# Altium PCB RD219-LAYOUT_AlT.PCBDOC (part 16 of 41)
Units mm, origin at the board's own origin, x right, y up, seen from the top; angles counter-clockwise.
Board outline 209.75 x 159.97 mm, 2 copper layers (TOP, BOTTOM), stack 0 mm thick; 398 components, 199 nets, 1469 pads, 0 vias.
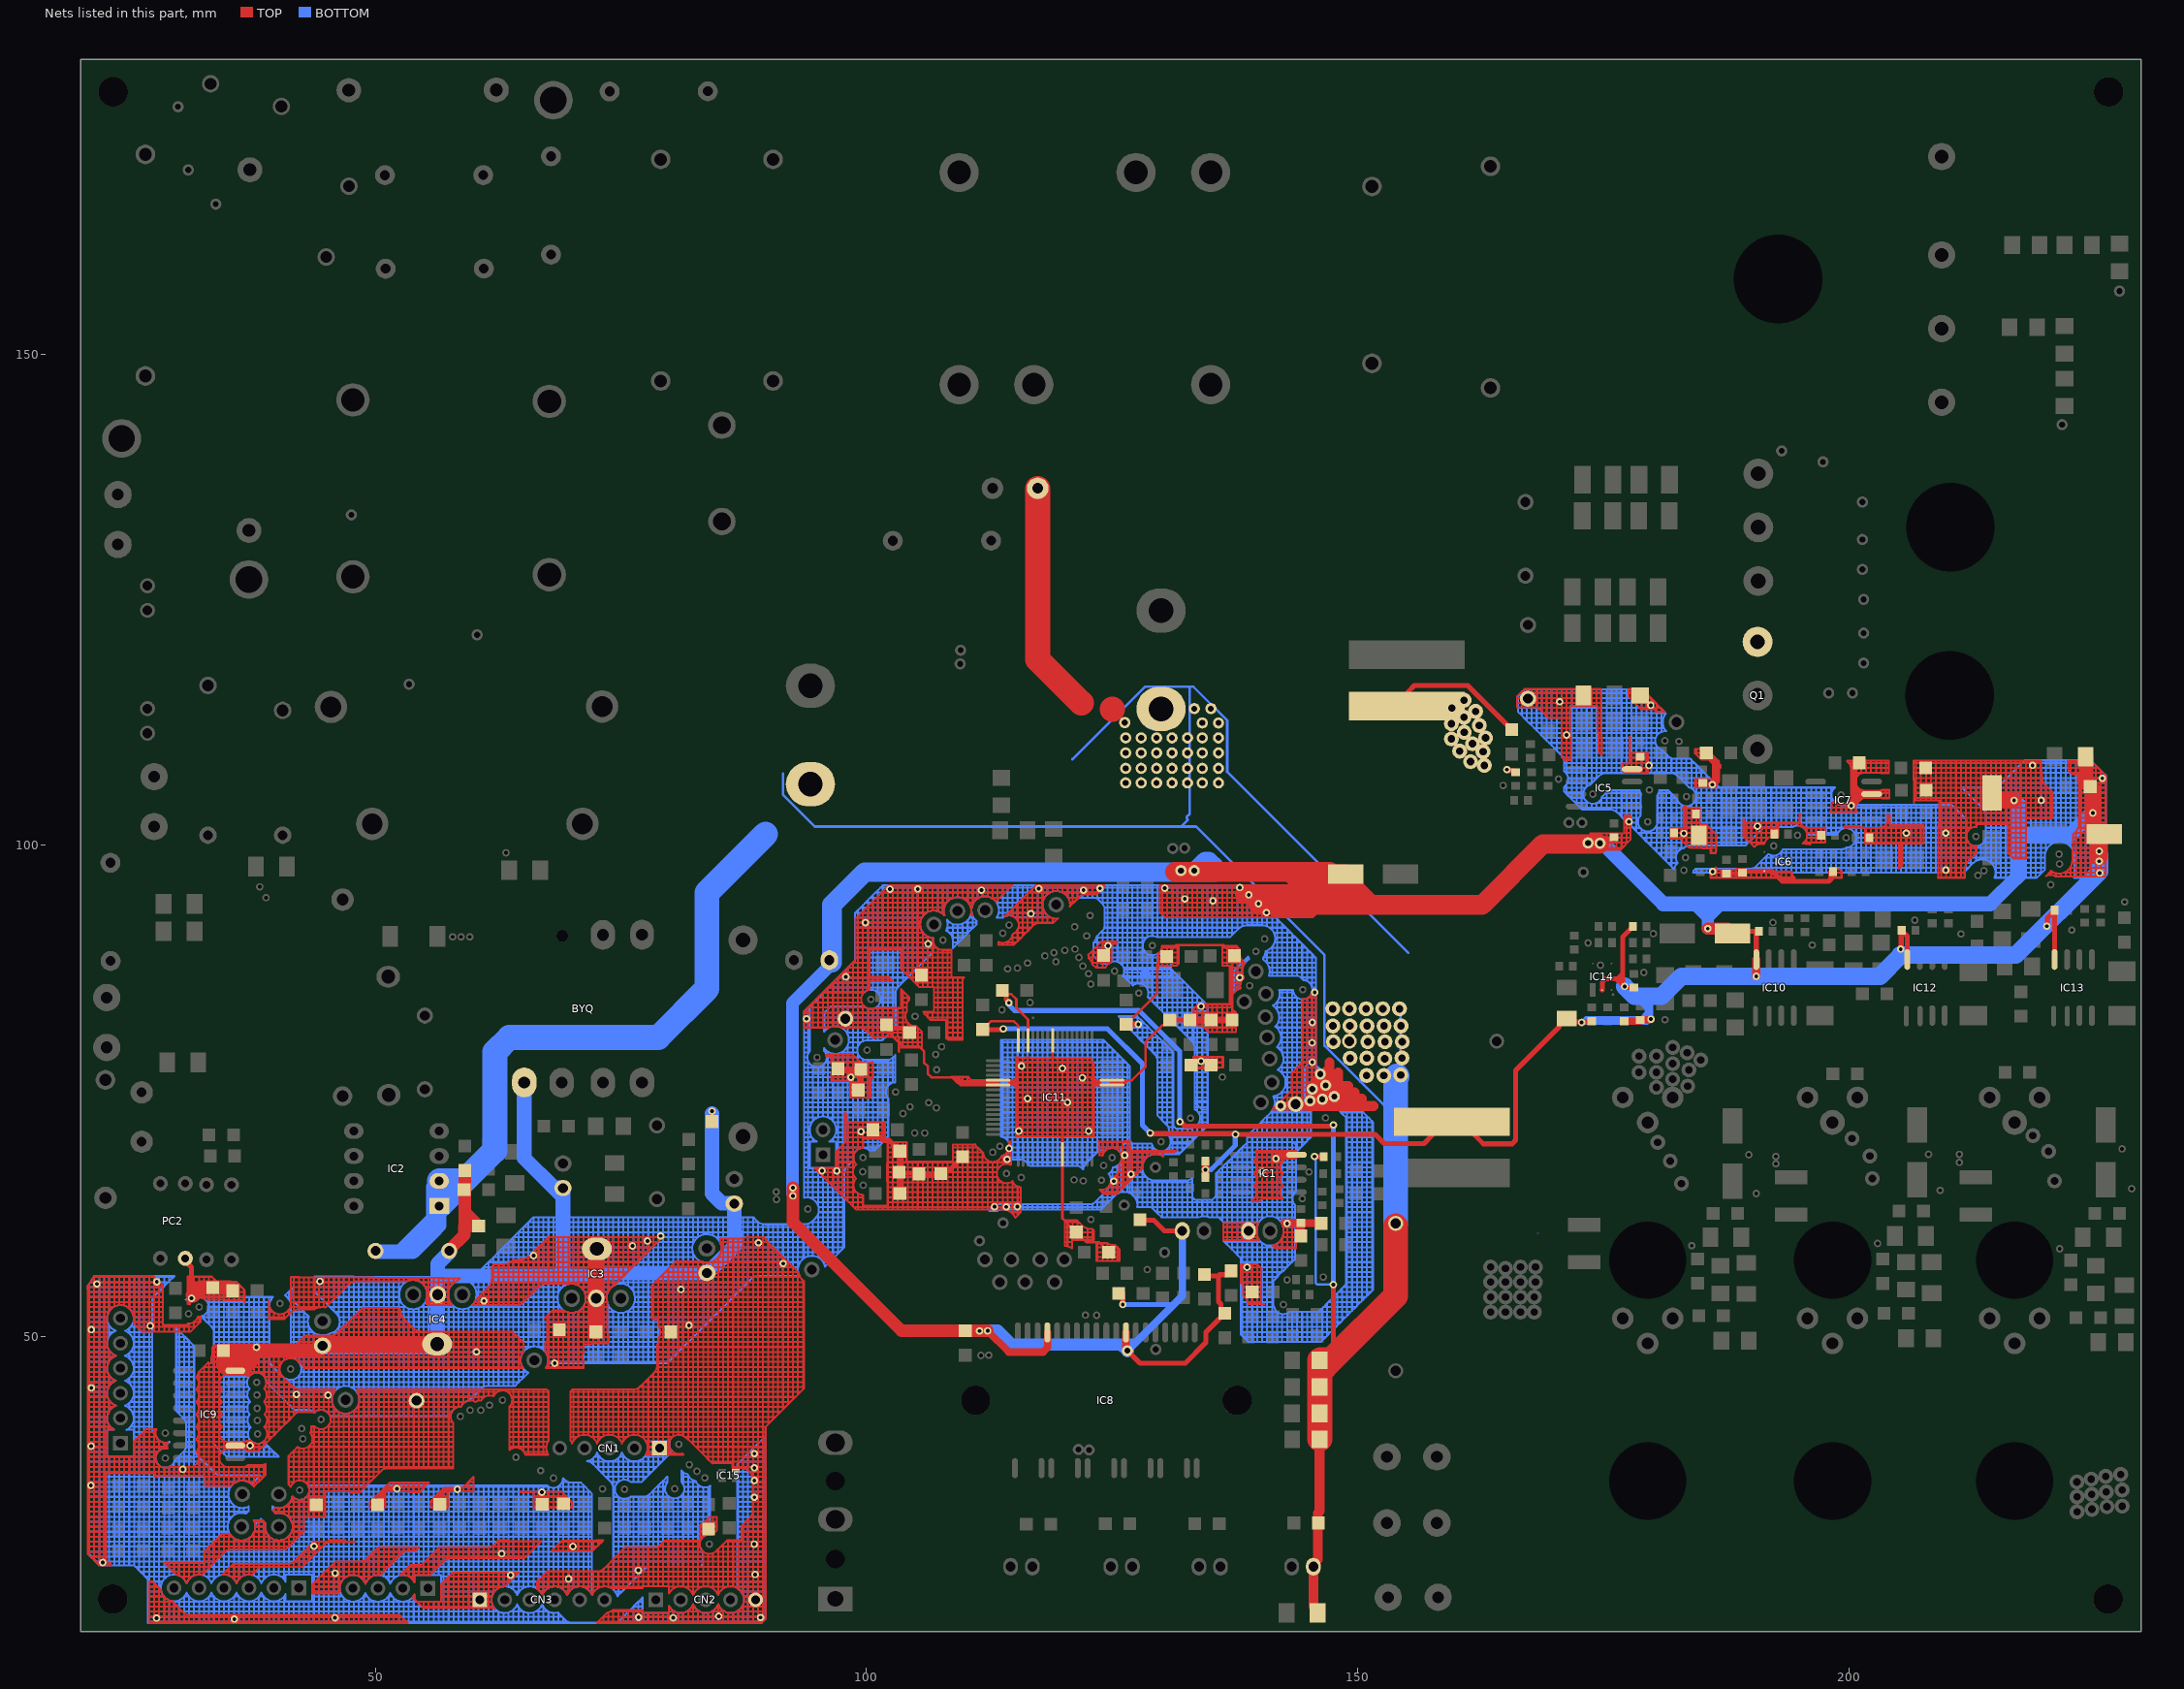
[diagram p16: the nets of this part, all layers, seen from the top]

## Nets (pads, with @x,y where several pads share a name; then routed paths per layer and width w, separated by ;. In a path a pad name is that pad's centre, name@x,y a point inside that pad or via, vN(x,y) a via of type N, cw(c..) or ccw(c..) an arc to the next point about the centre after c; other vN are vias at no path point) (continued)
GND: (continued)
  TOP w0.203: 145.349,75.88 145.349,76.388 ; 145.349,75.88 145.688,75.88 145.73,75.88 ; 145.349,76.388 145.349,76.896 ; 145.349,76.388 pad.@145.73,76.388 ; 145.349,76.896 145.349,77.404 ; 145.349,76.896 pad.@145.73,76.896 ; 145.349,77.404 pad.@145.349,77.912 ; 145.349,77.404 145.73,77.404 ; pad.@145.349,77.912 pad.@145.73,77.912 ; pad.@145.349,77.912 145.349,78.42 ; 145.349,78.42 145.349,78.928 ; 145.349,78.42 145.73,78.42 ; 145.349,78.928 145.349,79.436 ; 145.349,78.928 145.73,78.928 ; 145.349,79.436 145.73,79.436 ; 145.349,79.436 pad.@145.349,79.944 ; pad.@145.349,79.944 145.349,80.452 ; pad.@145.349,79.944 145.73,79.944 ; 145.349,80.452 145.349,80.96 ; 145.349,80.452 145.73,80.452 ; 145.349,80.96 145.349,81.468 ; 145.349,80.96 145.73,80.96 ; 145.349,81.468 pad.@145.349,81.976 ; 145.349,81.468 145.73,81.468 ; pad.@145.349,81.976 pad.@145.73,81.976 ; pad.@145.349,81.976 145.349,82.484 ; 145.349,82.484 145.349,82.992 ; 145.349,82.484 145.73,82.484 ; 145.349,82.992 145.349,83.5 ; 145.349,82.992 145.73,82.992 ; 145.349,83.5 145.349,84.008 ; 145.349,83.5 145.73,83.5 ; 145.349,84.008 145.349,84.516 ; 145.349,84.008 145.73,84.008 ; 145.349,84.516 pad.@145.349,85.006 ; 145.349,84.516 145.73,84.516 ; pad.@145.349,85.006 145.73,85.006 145.73,84.516 ; 145.73,74.356 145.73,74.833 pad.@145.73,74.864 ; pad.@145.73,74.864 pad.@145.73,75.372 ; pad.@145.73,75.372 145.73,75.392 145.73,75.88 ; 145.73,75.88 145.73,75.922 pad.@145.73,76.388 ; pad.@145.73,76.388 pad.@145.73,76.896 ; pad.@145.73,76.896 145.73,77.404 ; 145.73,77.404 pad.@145.73,77.912 ; pad.@145.73,77.912 145.73,78.42 ; 145.73,78.42 145.73,78.928 ; 145.73,78.928 145.73,79.436 ; 145.73,79.436 145.73,79.944 ; 145.73,79.944 145.73,80.452 ; 145.73,80.452 145.73,80.96 ; 145.73,80.96 145.73,81.468 ; 145.73,81.468 pad.@145.73,81.976 ; pad.@145.73,81.976 145.73,82.484 ; 145.73,82.484 145.73,82.992 ; 145.73,82.992 145.73,83.5 ; 145.73,83.5 145.73,84.008 ; 145.73,84.008 145.73,84.516 ; 166.211,114.488 166.211,114.996 ; 166.211,114.488 C62.1@166.685,114.488 ; 166.211,114.488 166.211,114.07 166.685,114.07 ; 166.211,114.996 166.211,115.153 166.562,115.504 ; 166.211,114.996 C62.1@166.685,114.996 ; 166.562,115.504 166.685,115.627 ; 166.562,115.504 166.685,115.504 ; 166.685,114.07 167.193,114.07 ; 166.685,114.07 C62.1@166.685,114.488 ; C62.1@166.685,114.488 C62.1@167.193,114.488 ; C62.1@166.685,114.488 C62.1@166.685,114.996 ; C62.1@166.685,114.996 166.685,115.504 ; C62.1@166.685,114.996 C62.1@167.193,114.996 ; 166.685,115.504 166.685,115.627 ; 166.685,115.504 C62.1@167.193,115.504 ; 166.685,115.627 166.973,115.915 167.193,115.915 ; 167.193,114.07 C62.1@167.193,114.488 ; 167.193,114.07 167.701,114.07 ; C62.1@167.193,114.488 C62.1@167.193,114.996 ; C62.1@167.193,114.488 C62.1@167.701,114.488 ; C62.1@167.193,114.996 C62.1@167.193,115.504 ; C62.1@167.193,114.996 C62.1@167.701,114.996 ; C62.1@167.193,115.504 167.193,115.915 ; C62.1@167.193,115.504 C62.1@167.701,115.504 ; 167.193,115.915 167.701,115.915 ; 167.701,114.07 C62.1@167.701,114.488 ; 167.701,114.07 167.955,114.07 ; C62.1@167.701,114.488 168.209,114.488 ; C62.1@167.701,114.488 C62.1@167.701,114.996 ; C62.1@167.701,114.996 C62.1@167.701,115.504 ; C62.1@167.701,114.996 168.209,114.996 ; C62.1@167.701,115.504 167.701,115.915 ; C62.1@167.701,115.504 168.209,115.504 ; 167.701,115.915 168.209,115.915 ; 167.955,114.07 cw(c167.955,113.218) 168.209,114.031 ; 167.955,114.07 cw(c167.955,113.218) 168.209,114.031 ; 168.209,114.031 cw(c167.955,113.218) 168.335,113.98 ; 168.209,114.031 cw(c167.955,113.218) 168.335,113.98 ; 168.209,114.031 168.209,114.488 ; 168.209,114.488 168.717,114.488 ; 168.209,114.488 168.209,114.996 ; 168.209,114.996 168.209,115.504 ; 168.209,114.996 168.717,114.996 ; 168.209,115.504 168.209,115.915 ; 168.209,115.504 168.717,115.504 ; 168.209,115.915 168.717,115.915 ; 168.335,113.98 cw(c167.955,113.218) 168.342,113.977 ; 168.335,113.98 cw(c167.955,113.218) 168.557,113.82 ccw(c167.955,113.218) 168.342,113.977 ; 168.335,113.98 cw(c167.955,113.218) 168.342,113.977 ; 168.335,113.98 168.717,113.98 ; 168.717,113.66 168.905,113.472 ; 168.717,113.66 168.717,113.98 ; 168.717,113.98 168.717,114.488 ; 168.717,113.98 169.225,113.98 ; 168.717,114.488 168.717,114.996 ; 168.717,114.488 169.225,114.488 ; 168.717,114.996 168.717,115.504 ; 168.717,114.996 169.225,114.996 ; 168.717,115.504 168.717,115.915 ; 168.717,115.504 169.225,115.504 ; 168.717,115.915 169.225,115.915 ; 168.905,113.472 169.225,113.472 ; 168.905,113.472 169.225,113.152 ; 169.225,113.152 169.413,112.964 ; 169.225,113.152 169.225,113.472 ; 169.225,113.472 169.225,113.98 ; 169.225,113.472 169.733,113.472 ; 169.225,113.98 169.225,114.488 ; 169.225,113.98 169.733,113.98 ; 169.225,114.488 169.225,114.996 ; 169.225,114.488 169.733,114.488 ; 169.225,114.996 169.225,115.504 ; 169.225,114.996 169.733,114.996 ; 169.225,115.504 169.225,115.915 ; 169.225,115.504 169.733,115.504 ; 169.225,115.915 169.733,115.915 ; 169.413,112.964 169.432,112.946 169.733,112.946 ; 169.413,112.964 169.733,112.964 ; 169.733,112.946 169.733,112.964 ; 169.733,112.946 170.241,112.946 ; 169.733,112.964 169.733,113.472 ; 169.733,112.964 170.241,112.964 ; 169.733,113.472 169.733,113.98 ; 169.733,113.472 170.241,113.472 ; 169.733,113.98 169.733,114.488 ; 169.733,113.98 170.241,113.98 ; 169.733,114.488 169.733,114.996 ; 169.733,114.488 pad.@170.241,114.488 ; 169.733,114.996 169.733,115.504 ; 169.733,114.996 170.241,114.996 ; 169.733,115.504 169.733,115.915 ; 169.733,115.504 170.241,115.504 ; 169.733,115.915 170.241,115.915 ; 170.241,112.946 170.241,112.964 ; 170.241,112.946 170.731,112.946 170.731,112.456 ; 170.241,112.964 170.749,112.964 ; 170.241,112.964 170.241,113.472 ; 170.241,113.472 170.241,113.98 ; 170.241,113.472 170.749,113.472 ; 170.241,113.98 pad.@170.241,114.488 ; 170.241,113.98 170.749,113.98 ; pad.@170.241,114.488 170.241,114.996 ; pad.@170.241,114.488 pad.@170.749,114.488 ; 170.241,114.996 170.241,115.504 ; 170.241,114.996 170.749,114.996 ; 170.241,115.504 170.241,115.915 ; 170.241,115.504 170.749,115.504 ; 170.241,115.915 170.749,115.915 ; 170.731,109.408 170.749,109.408 ; 170.731,109.408 170.731,109.916 ; 170.731,109.408 170.731,108.983 170.749,108.964 ; 170.731,109.916 170.731,110.424 ; 170.731,109.916 170.749,109.916 ; 170.731,110.424 170.749,110.424 ; 170.731,110.932 170.749,110.932 ; 170.731,110.932 170.731,111.44 ; 170.731,111.44 170.749,111.44 ; 170.731,111.44 170.731,111.948 ; 170.731,111.948 170.749,111.948 ; 170.731,111.948 170.731,112.456 ; 170.731,112.456 170.749,112.456 ; 170.749,108.964 170.813,108.9 ; 170.749,108.964 170.749,109.408 ; 170.749,109.408 170.749,109.916 ; 170.749,109.408 171.257,109.408 ; 170.749,109.916 170.749,110.424 ; 170.749,109.916 171.257,109.916 ; 170.749,110.424 171.257,110.424 ; 170.749,110.424 170.749,110.932 ; 170.749,110.932 170.749,111.44 ; 170.749,110.932 pad.@171.257,110.932 ; 170.749,111.44 170.749,111.948 ; 170.749,111.44 pad.@171.257,111.44 ; 170.749,111.948 170.749,112.456 ; 170.749,111.948 171.257,111.948 ; 170.749,112.456 170.749,112.964 ; 170.749,112.456 171.257,112.456 ; 170.749,112.964 171.257,112.964 ; 170.749,112.964 170.749,113.472 ; 170.749,113.472 170.749,113.98 ; 170.749,113.472 171.257,113.472 ; 170.749,113.98 pad.@170.749,114.488 ; 170.749,113.98 171.257,113.98 ; pad.@170.749,114.488 171.257,114.488 ; pad.@170.749,114.488 170.749,114.996 ; 170.749,114.996 171.257,114.996 ; 170.749,114.996 170.749,115.504 ; 170.749,115.504 170.749,115.915 ; 170.749,115.504 171.257,115.504 ; 170.749,115.915 171.257,115.915 ; 170.813,108.9 171.257,108.9 ; 171.257,108.634 cw(c171.467,107.757) 171.467,108.659 171.706,108.659 171.706,108.9 ; 171.257,108.634 171.257,108.9 ; 171.257,108.9 171.706,108.9 ; 171.257,108.9 171.257,109.408 ; 171.257,109.408 171.257,109.916 ; 171.257,109.408 171.706,109.408 ; 171.257,109.916 171.257,110.424 ; 171.257,109.916 171.706,109.916 ; 171.257,110.424 pad.@171.257,110.932 ; 171.257,110.424 171.706,110.424 ; pad.@171.257,110.932 171.706,110.932 ; pad.@171.257,110.932 pad.@171.257,111.44 ; pad.@171.257,111.44 171.257,111.948 ; pad.@171.257,111.44 171.579,111.44 ; 171.257,111.948 171.257,112.456 ; 171.257,111.948 171.579,111.948 ; 171.257,112.456 171.257,112.964 ; 171.257,112.456 171.579,112.456 ; 171.257,112.964 171.257,113.472 ; 171.257,112.964 171.579,112.964 ; 171.257,113.472 171.257,113.98 ; 171.257,113.472 171.579,113.472 ; 171.257,113.98 171.257,114.488 ; 171.257,113.98 171.579,113.98 ; 171.257,114.488 171.257,114.996 ; 171.257,114.488 171.765,114.488 ; 171.257,114.996 171.765,114.996 ; 171.257,114.996 171.257,115.504 ; 171.257,115.504 171.257,115.915 ; 171.257,115.504 171.765,115.504 ; 171.257,115.915 171.765,115.915 ; 171.579,111.44 171.579,111.948 ; 171.579,111.44 171.579,110.981 171.706,110.981 171.706,110.932 ; 171.579,111.948 171.579,112.456 ; 171.579,112.456 171.579,112.964 ; 171.579,112.964 171.579,113.472 ; 171.579,113.472 171.579,113.98 ; 171.579,113.98 171.579,114.185 171.765,114.185 ; 171.706,108.9 171.706,109.408 ; 171.706,109.408 171.706,109.916 ; 171.706,109.916 171.706,110.424 ; 171.706,110.424 171.706,110.932 ; 171.765,114.185 172.273,114.185 ; 171.765,114.185 171.765,114.488 ; 171.765,114.488 171.765,114.996 ; 171.765,114.488 ZD8.1@172.273,114.488 ; 171.765,114.996 ZD8.1@172.273,114.996 ; 171.765,114.996 171.765,115.504 ; 171.765,115.504 171.765,115.915 ; 171.765,115.504 ZD8.1@172.273,115.504 ; 171.765,115.915 ZD8.1@172.273,115.915 ; 172.273,114.185 ZD8.1@172.273,114.488 ; 172.273,114.185 172.781,114.185 ; ZD8.1@172.273,114.488 ZD8.1@172.273,114.996 ; ZD8.1@172.273,114.488 ZD8.1@172.781,114.488 ; ZD8.1@172.273,114.996 ZD8.1@172.781,114.996 ; ZD8.1@172.273,114.996 ZD8.1@172.273,115.504 ; ZD8.1@172.273,115.504 ZD8.1@172.273,115.915 ; ZD8.1@172.273,115.504 ZD8.1@172.781,115.504 ; ZD8.1@172.273,115.915 ZD8.1@172.781,115.915 ; 172.781,114.185 ZD8.1@172.781,114.488 ; 172.781,114.185 173.289,114.185 ; ZD8.1@172.781,114.488 ZD8.1@172.781,114.996 ; ZD8.1@172.781,114.488 ZD8.1@173.289,114.488 ; ZD8.1@172.781,114.996 ZD8.1@172.781,115.504 ; ZD8.1@172.781,114.996 ZD8.1@173.289,114.996 ; ZD8.1@172.781,115.504 ZD8.1@172.781,115.915 ; ZD8.1@172.781,115.504 ZD8.1@173.289,115.504 ; ZD8.1@172.781,115.915 ZD8.1@173.289,115.915 ; 173.289,114.185 ZD8.1@173.289,114.488 ; 173.289,114.185 173.797,114.185 ; ZD8.1@173.289,114.488 ZD8.1@173.289,114.996 ; ZD8.1@173.289,114.488 173.797,114.488 ; ZD8.1@173.289,114.996 173.797,114.996 ; ZD8.1@173.289,114.996 ZD8.1@173.289,115.504 ; ZD8.1@173.289,115.504 ZD8.1@173.289,115.915 ; ZD8.1@173.289,115.504 173.797,115.504 ; ZD8.1@173.289,115.915 173.797,115.915 ; 173.797,101.026 174.051,100.772 ; 173.797,101.026 173.797,101.213 ; 173.797,101.213 174.305,101.213 ; 173.797,114.185 174.305,114.185 ; 173.797,114.185 173.797,114.488 ; 173.797,114.488 173.797,114.996 ; 173.797,114.488 174.305,114.488 ; 173.797,114.996 174.305,114.996 ; 173.797,114.996 173.797,115.504 ; 173.797,115.504 173.797,115.915 ; 173.797,115.504 174.305,115.504 ; 173.797,115.915 174.305,115.915 ; 174.051,100.772 174.305,100.772 ; 174.051,100.772 pad.@174.305,100.518 ; pad.@174.305,100.518 174.305,100.772 ; pad.@174.305,100.518 pad.@174.559,100.264 ; 174.305,100.772 174.305,101.213 ; 174.305,100.772 174.813,100.772 ; 174.305,101.213 174.813,101.213 ; 174.305,114.185 174.383,114.185 174.383,113.98 ; 174.305,114.185 174.305,114.488 ; 174.305,114.488 174.305,114.996 ; 174.305,114.488 174.735,114.488 ; 174.305,114.996 174.735,114.996 ; 174.305,114.996 174.305,115.504 ; 174.305,115.504 174.305,115.915 ; 174.305,115.504 174.735,115.504 ; 174.305,115.915 174.735,115.915 174.735,115.504 ; 174.383,111.948 174.383,112.456 ; 174.383,111.948 174.383,111.518 174.51,111.518 174.51,111.44 ; 174.383,111.948 174.735,111.948 ; 174.383,112.456 174.383,112.964 ; 174.383,112.456 174.735,112.456 ; 174.383,112.964 174.383,113.472 ; 174.383,112.964 174.735,112.964 ; 174.383,113.472 174.383,113.98 ; 174.383,113.472 174.735,113.472 ; 174.383,113.98 174.735,113.98 ; 174.51,109.916 174.813,109.916 ; 174.51,109.916 174.51,110.424 ; 174.51,109.916 174.51,109.519 174.62,109.408 ; 174.51,110.424 174.51,110.932 ; 174.51,110.424 174.813,110.424 ; 174.51,110.932 174.813,110.932 ; 174.51,110.932 174.51,111.44 ; 174.51,111.44 174.735,111.44 ; pad.@174.559,100.264 pad.@174.813,100.01 ; pad.@174.559,100.264 pad.@174.813,100.264 ; 174.62,109.408 174.813,109.408 ; 174.62,109.408 174.813,109.215 ; 174.735,111.44 174.735,111.948 ; 174.735,111.44 174.735,110.981 174.813,110.981 ; 174.735,111.948 174.735,112.456 ; 174.735,112.456 174.735,112.964 ; 174.735,112.964 174.735,113.472 ; 174.735,113.472 174.735,113.98 ; 174.735,113.98 174.735,114.488 ; 174.735,114.488 174.735,114.996 ; 174.735,114.996 174.735,115.504 ; pad.@174.813,100.01 175.067,99.756 ; pad.@174.813,100.01 174.813,100.219 pad.@174.813,100.264 ; pad.@174.813,100.264 174.813,100.772 ; pad.@174.813,100.264 174.874,100.264 175.321,100.264 ; 174.813,100.772 175.321,100.772 ; 174.813,100.772 174.813,101.213 ; 174.813,101.213 175.321,101.213 ; 174.813,109.215 174.862,109.166 174.862,109.408 ; 174.813,109.215 174.813,109.408 ; 174.813,109.408 174.862,109.408 ; 174.813,109.408 174.813,109.916 ; 174.813,109.916 174.813,110.424 ; 174.813,109.916 174.862,109.916 ; 174.813,110.424 174.813,110.932 ; 174.813,110.424 174.862,110.424 ; 174.813,110.932 174.862,110.932 ; 174.813,110.932 174.813,110.981 ; 174.813,110.981 174.862,110.981 174.862,110.932 ; 174.862,109.408 174.862,109.916 ; 174.862,109.916 174.862,110.424 ; 174.862,110.424 174.862,110.932 ; 175.067,99.756 175.274,99.549 175.321,99.549 ; 175.067,99.756 175.321,99.756 ; 175.321,99.549 175.321,99.756 ; 175.321,99.549 175.829,99.549 ; 175.321,99.756 175.829,99.756 ; 175.321,99.756 175.321,100.264 ; 175.321,100.264 175.829,100.264 ; 175.321,100.264 175.321,100.688 175.321,100.772 ; 175.321,100.772 C15.1@175.829,100.772 ; 175.321,100.772 175.321,101.213 ; 175.321,101.213 C15.1@175.829,101.213 ; 175.829,99.549 176.337,99.549 ; 175.829,99.549 175.829,99.756 ; 175.829,99.756 176.337,99.756 ; 175.829,99.756 175.829,100.264 ; 175.829,100.264 176.337,100.264 ; 175.829,100.264 175.829,100.688 C15.1@175.829,100.772 ; C15.1@175.829,100.772 176.021,100.772 C15.1@176.337,100.772 ; C15.1@175.829,100.772 C15.1@175.829,101.213 ; C15.1@175.829,101.213 C15.1@176.002,101.213 ; C15.1@176.002,101.213 ccw(c176.002,102.315) C15.1@176.206,101.232 ; C15.1@176.002,101.213 ccw(c176.002,102.315) C15.1@176.206,101.232 ; C15.1@176.206,101.232 ccw(c176.002,102.315) 176.212,101.234 cw(c176.002,102.315) C15.1@176.206,101.232 ; C15.1@176.206,101.232 C15.1@176.337,101.232 ; 176.337,99.549 176.718,99.549 177.744,100.575 177.744,100.772 ; 176.337,99.549 176.337,99.756 ; 176.337,99.756 176.845,99.756 ; 176.337,99.756 176.337,100.264 ; 176.337,100.264 176.845,100.264 ; 176.337,100.264 C15.1@176.337,100.772 ; C15.1@176.337,100.772 176.845,100.772 ; C15.1@176.337,100.772 C15.1@176.337,101.232 ; C15.1@176.337,101.232 176.845,101.232 ; 176.845,99.756 176.845,100.264 ; 176.845,100.264 177.353,100.264 ; 176.845,100.264 176.845,100.772 ; 176.845,100.772 177.353,100.772 ; 176.845,100.772 176.845,101.232 ; 176.845,101.232 177.135,101.232 177.135,101.28 ; IC5.4@176.939,107.884 176.939,108.314 177.353,108.314 ; IC5.4@176.939,107.884 IC5.4@177.353,107.884 ; 177.135,101.28 177.135,101.788 ; 177.135,101.28 177.353,101.28 ; 177.135,101.788 177.353,101.788 ; 177.135,101.788 177.135,102.296 ; 177.135,102.296 pad.@177.353,102.296 ; 177.135,102.296 177.135,102.804 ; 177.135,102.804 177.353,102.804 ; 177.353,100.264 177.353,100.772 ; 177.353,100.772 177.353,101.28 ; 177.353,100.772 177.744,100.772 ; 177.353,101.28 177.353,101.788 ; 177.353,101.28 177.744,101.28 ; 177.353,101.788 pad.@177.353,102.296 ; 177.353,101.788 177.744,101.788 ; pad.@177.353,102.296 177.353,102.804 ; pad.@177.353,102.296 pad.@177.744,102.296 ; 177.353,102.804 177.353,103.045 ; 177.353,102.804 177.744,102.804 ; 177.353,103.045 177.744,103.045 177.744,102.804 ; 177.353,107.389 177.861,107.389 ; 177.353,107.389 IC5.4@177.353,107.884 ; IC5.4@177.353,107.884 177.353,108.314 ; IC5.4@177.353,107.884 IC5.4@177.861,107.884 ; 177.353,108.314 177.666,108.314 177.666,108.392 ; 177.539,115.504 R135.2@177.861,115.504 ; 177.539,115.504 177.539,115.915 R135.2@177.861,115.915 ; 177.666,108.392 177.666,108.9 ; 177.666,108.392 177.861,108.392 ; 177.666,108.9 177.666,109.408 ; 177.666,108.9 177.861,108.9 ; 177.666,109.408 177.861,109.408 ; 177.744,100.772 177.744,101.28 ; 177.744,101.28 177.744,101.788 ; 177.744,101.788 pad.@177.744,102.296 ; pad.@177.744,102.296 177.744,102.804 ; 177.861,107.389 IC5.4@177.861,107.884 ; 177.861,107.389 178.369,107.389 ; IC5.4@177.861,107.884 177.861,108.392 ; IC5.4@177.861,107.884 IC5.4@178.369,107.884 ; 177.861,108.392 177.861,108.9 ; 177.861,108.392 178.369,108.392 ; 177.861,108.9 177.861,109.408 ; 177.861,108.9 C27.2@178.369,108.9 ; 177.861,109.408 C27.2@178.369,109.408 ; 177.861,109.408 177.861,109.422 ; 177.861,109.422 C27.2@178.369,109.422 ; R135.2@177.861,114.996 R135.2@178.369,114.996 ; R135.2@177.861,114.996 R135.2@177.861,115.504 ; R135.2@177.861,115.504 R135.2@177.861,115.915 ; R135.2@177.861,115.504 R135.2@178.369,115.504 ; R135.2@177.861,115.915 R135.2@178.369,115.915 ; R135.2@178.212,114.488 cw(c177.496,113.815) 178.306,114.37 ; R135.2@178.212,114.488 ccw(c177.496,113.815) 178.191,114.509 cw(c177.496,113.815) R135.2@178.212,114.488 ; R135.2@178.212,114.488 cw(c177.496,113.815) 178.306,114.37 ; R135.2@178.212,114.488 R135.2@178.369,114.488 ; 178.306,114.37 cw(c177.496,113.815) 178.311,114.364 ccw(c177.496,113.815) 178.306,114.37 ; 178.306,114.37 178.697,113.98 ; 178.369,107.389 178.667,107.389 cw(c178.667,106.487) 178.817,107.376 ; 178.369,107.389 IC5.4@178.369,107.884 ; IC5.4@178.369,107.884 178.369,108.392 ; IC5.4@178.369,107.884 IC5.4@178.877,107.884 ; 178.369,108.392 C27.2@178.369,108.9 ; 178.369,108.392 178.877,108.392 ; C27.2@178.369,108.9 C27.2@178.877,108.9 ; C27.2@178.369,108.9 C27.2@178.369,109.408 ; C27.2@178.369,109.408 C27.2@178.369,109.422 ; C27.2@178.369,109.408 C27.2@178.877,109.408 ; C27.2@178.369,109.422 C27.2@178.877,109.422 ; R135.2@178.369,114.488 R135.2@178.369,114.996 ; R135.2@178.369,114.488 R135.2@178.877,114.488 ; R135.2@178.369,114.996 R135.2@178.369,115.504 ; R135.2@178.369,114.996 R135.2@178.877,114.996 ; R135.2@178.369,115.504 R135.2@178.369,115.915 ; R135.2@178.369,115.504 R135.2@178.877,115.504 ; R135.2@178.369,115.915 R135.2@178.877,115.915 ; 178.697,113.98 178.877,113.98 ; 178.697,113.98 178.822,113.855 178.877,113.855 ; 178.817,107.376 cw(c178.667,106.487) 178.877,107.364 ; 178.817,107.376 178.877,107.376 ; 178.877,107.364 178.877,107.376 ; 178.877,107.376 179.385,107.376 ; 178.877,107.376 IC5.4@178.877,107.884 ; IC5.4@178.877,107.884 178.877,108.392 ; IC5.4@178.877,107.884 pad.@179.385,107.884 ; 178.877,108.392 C27.2@178.877,108.9 ; 178.877,108.392 pad.@179.385,108.392 ; C27.2@178.877,108.9 179.385,108.9 ; C27.2@178.877,108.9 C27.2@178.877,109.408 ; C27.2@178.877,109.408 179.385,109.408 ; C27.2@178.877,109.408 C27.2@178.877,109.422 ; C27.2@178.877,109.422 179.385,109.422 ; 178.877,113.855 178.877,113.98 ; 178.877,113.855 179.385,113.855 ; 178.877,113.98 179.385,113.98 ; 178.877,113.98 R135.2@178.877,114.488 ; R135.2@178.877,114.488 R135.2@179.385,114.488 ; R135.2@178.877,114.488 R135.2@178.877,114.996 ; R135.2@178.877,114.996 R135.2@179.385,114.996 ; R135.2@178.877,114.996 R135.2@178.877,115.504 ; R135.2@178.877,115.504 R135.2@178.877,115.915 ; R135.2@178.877,115.504 R135.2@179.322,115.504 ; R135.2@178.877,115.915 178.911,115.915 R135.2@179.322,115.504 ; R135.2@179.322,115.504 R135.2@179.385,115.441 ; 179.385,107.343 179.385,107.376 ; 179.385,107.343 179.53,107.343 179.53,107.376 ; 179.385,107.376 pad.@179.385,107.884 ; 179.385,107.376 179.53,107.376 ; pad.@179.385,107.884 pad.@179.53,107.884 ; pad.@179.385,107.884 pad.@179.385,108.392 ; pad.@179.385,108.392 179.385,108.9 ; pad.@179.385,108.392 pad.@179.53,108.392 ; 179.385,108.9 179.385,109.408 ; 179.385,108.9 179.53,108.9 ; 179.385,109.408 179.53,109.408 ; 179.385,109.408 179.385,109.422 ; 179.385,109.422 179.53,109.422 179.53,109.408 ; 179.385,113.855 179.385,113.98 ; 179.385,113.855 179.893,113.855 ; 179.385,113.98 pad.@179.893,113.98 ; 179.385,113.98 R135.2@179.385,114.488 ; R135.2@179.385,114.488 R135.2@179.385,114.996 ; R135.2@179.385,114.488 pad.@179.893,114.488 ; R135.2@179.385,114.996 179.83,114.996 ; R135.2@179.385,114.996 R135.2@179.385,115.441 ; R135.2@179.385,115.441 179.83,114.996 ; 179.53,107.376 pad.@179.53,107.884 ; pad.@179.53,108.392 179.53,108.9 ; 179.53,108.9 179.53,109.408 ; 179.83,114.996 179.893,114.933 ; 179.893,113.855 pad.@179.893,113.98 ; 179.893,113.855 180.252,113.855 180.252,113.585 180.401,113.585 ; pad.@179.893,113.98 180.401,113.98 ; pad.@179.893,113.98 pad.@179.893,114.488 ; pad.@179.893,114.488 180.338,114.488 ; pad.@179.893,114.488 179.893,114.933 ; 179.893,114.933 180.338,114.488 ; 180.338,114.488 180.401,114.425 ; 180.401,113.585 180.401,113.98 ; 180.401,113.585 180.909,113.585 ; 180.401,113.98 180.401,114.425 ; 180.401,113.98 180.846,113.98 ; 180.401,114.425 180.846,113.98 ; 180.846,113.98 180.909,113.917 ; 180.909,113.585 180.909,113.917 ; 181.781,100.772 181.781,100.703 181.925,100.703 ; 181.781,100.772 181.925,100.772 ; 181.781,100.772 R32.2@181.781,101.28 ; R32.2@181.781,101.28 R32.2@181.925,101.28 ; R32.2@181.781,101.28 181.781,101.752 181.925,101.752 ; 181.925,100.703 181.925,100.772 ; 181.925,100.703 182.433,100.703 ; 181.925,100.772 182.433,100.772 ; 181.925,100.772 R32.2@181.925,101.28 ; R32.2@181.925,101.28 R32.2@182.179,101.28 R32.2@182.433,101.28 ; R32.2@181.925,101.28 181.925,101.752 ; 181.925,101.752 182.433,101.752 ; 182.433,100.703 182.433,100.772 ; 182.433,100.703 182.941,100.703 ; 182.433,100.772 182.941,100.772 ; 182.433,100.772 R32.2@182.433,101.28 ; R32.2@182.433,101.28 pad.@182.941,101.28 ; R32.2@182.433,101.28 182.433,101.752 ; 182.433,101.752 182.941,101.752 ; 182.941,100.703 182.941,100.772 ; 182.941,100.703 183.05,100.703 183.05,100.321 ; 182.941,100.772 183.449,100.772 ; 182.941,100.772 pad.@182.941,101.28 ; pad.@182.941,101.28 182.941,101.752 ; pad.@182.941,101.28 pad.@183.449,101.28 ; 182.941,101.752 183.181,101.752 183.181,101.788 ; 183.05,100.321 cw(c182.634,99.301) 183.169,100.264 ; 183.05,100.321 ccw(c182.634,99.301) 183.046,100.323 cw(c182.634,99.301) 183.05,100.321 ; 183.05,100.321 cw(c182.634,99.301) 183.169,100.264 ; 183.169,100.264 cw(c182.634,99.301) 183.413,100.08 ; 183.169,100.264 cw(c182.634,99.301) 183.413,100.08 ; 183.169,100.264 183.449,100.264 ; 183.181,101.788 183.181,102.296 ; 183.181,101.788 183.449,101.788 ; 183.181,102.296 183.181,102.804 ; 183.181,102.296 183.449,102.296 ; 183.181,102.804 183.449,102.804 ; 183.181,102.804 183.181,103.312 ; 183.181,103.312 183.449,103.312 ; 183.246,103.82 183.398,103.82 ; 183.246,103.82 183.246,104.002 ccw(c183.449,104.963) 183.398,103.982 183.398,103.82 ; 183.398,103.82 183.398,103.784 183.449,103.784 ; 183.449,100.264 183.449,100.772 ; 183.449,100.264 D7.1@183.957,100.264 ; 183.449,100.772 D7.1@183.957,100.772 ; 183.449,100.772 pad.@183.449,101.28 ; pad.@183.449,101.28 183.449,101.788 ; pad.@183.449,101.28 D7.1@183.957,101.28 ; 183.449,101.788 183.449,102.296 ; 183.449,101.788 D7.1@183.957,101.788 ; 183.449,102.296 183.449,102.804 ; 183.449,102.296 183.957,102.296 ; 183.449,102.804 183.449,103.312 ; 183.449,102.804 183.957,102.804 ; 183.449,103.312 183.449,103.784 ; 183.449,103.312 183.957,103.312 ; 183.449,103.784 183.957,103.784 ; 183.817,99.756 cw(c183.356,98.756) 183.832,99.749 ; 183.817,99.756 183.957,99.756 ; 183.832,99.749 183.957,99.749 ; 183.957,99.749 183.957,99.756 ; 183.957,99.749 184.465,99.749 ; 183.957,99.756 D7.1@183.957,100.264 ; 183.957,99.756 184.465,99.756 ; D7.1@183.957,100.264 D7.1@183.957,100.772 ; D7.1@183.957,100.264 D7.1@184.465,100.264 ; D7.1@183.957,100.772 D7.1@184.465,100.772 ; D7.1@183.957,100.772 D7.1@183.957,101.28 ; D7.1@183.957,101.28 D7.1@183.957,101.788 ; D7.1@183.957,101.28 D7.1@184.465,101.28 ; D7.1@183.957,101.788 183.957,102.296 ; D7.1@183.957,101.788 D7.1@184.465,101.788 ; 183.957,102.296 183.957,102.804 ; 183.957,102.296 184.465,102.296 ; 183.957,102.804 C13.1@184.465,102.804 ; 183.957,102.804 183.957,103.312 ; 183.957,103.312 183.957,103.784 ; 183.957,103.312 C13.1@184.465,103.312 ; 183.957,103.784 184.465,103.784 ; 184.32,106.36 184.465,106.36 ; 184.32,106.36 184.32,106.744 184.465,106.744 ; 184.32,106.36 184.32,105.888 184.465,105.888 ; 184.32,109.408 184.465,109.408 ; 184.32,109.408 184.32,109.803 184.465,109.803 ; 184.32,109.408 184.32,109.366 184.465,109.221 ; 184.465,99.749 184.465,99.756 ; 184.465,99.749 184.815,99.749 cw(c184.815,98.647) 184.973,99.738 ; 184.465,99.756 184.973,99.756 ; 184.465,99.756 D7.1@184.465,100.264 ; D7.1@184.465,100.264 D7.1@184.465,100.772 ; D7.1@184.465,100.264 D7.1@184.973,100.264 ; D7.1@184.465,100.772 D7.1@184.973,100.772 ; D7.1@184.465,100.772 D7.1@184.465,101.28 ; D7.1@184.465,101.28 D7.1@184.465,101.788 ; D7.1@184.465,101.28 D7.1@184.973,101.28 ; D7.1@184.465,101.788 184.465,102.296 ; D7.1@184.465,101.788 D7.1@184.973,101.788 ; 184.465,102.296 C13.1@184.465,102.804 ; 184.465,102.296 184.798,102.296 ; C13.1@184.465,102.804 C13.1@184.798,102.804 ; C13.1@184.465,102.804 C13.1@184.465,103.312 ; C13.1@184.465,103.312 184.465,103.784 ; C13.1@184.465,103.312 C13.1@184.798,103.312 ; 184.465,103.784 184.798,103.784 C13.1@184.798,103.312 ; 184.465,105.888 184.973,105.888 ; 184.465,105.888 184.465,106.36 ; 184.465,106.36 C26.1@184.973,106.36 ; 184.465,106.36 184.465,106.744 ; 184.465,106.744 C26.1@184.973,106.744 ; 184.465,109.221 184.465,109.408 ; 184.465,109.408 C9.1@184.973,109.408 ; 184.465,109.408 184.465,109.803 ; 184.465,109.803 C9.1@184.973,109.803 ; 184.798,102.296 C13.1@184.798,102.804 ; 184.798,102.296 184.798,102.133 184.973,102.133 ; C13.1@184.798,102.804 C13.1@184.798,103.312 ; 184.973,99.738 184.973,99.756 ; 184.973,99.756 D7.1@184.973,100.264 ; 184.973,99.756 185.481,99.756 ; D7.1@184.973,100.264 D7.1@185.481,100.264 ; D7.1@184.973,100.264 D7.1@184.973,100.772 ; D7.1@184.973,100.772 D7.1@185.481,100.772 ; D7.1@184.973,100.772 D7.1@184.973,101.28 ; D7.1@184.973,101.28 D7.1@185.481,101.28 ; D7.1@184.973,101.28 D7.1@184.973,101.788 ; D7.1@184.973,101.788 D7.1@185.481,101.788 ; D7.1@184.973,101.788 184.973,102.133 ; 184.973,105.888 185.481,105.888 ; 184.973,105.888 C26.1@184.973,106.36 ; C26.1@184.973,106.36 C26.1@184.973,106.744 ; C26.1@184.973,106.36 C26.1@185.481,106.36 ; C26.1@184.973,106.744 C26.1@185.481,106.744 ; 184.973,108.747 C9.1@184.973,108.9 ; 184.973,108.747 185.481,108.747 ; C9.1@184.973,108.9 C9.1@185.481,108.9 ; C9.1@184.973,108.9 C9.1@184.973,109.408 ; C9.1@184.973,109.408 C9.1@185.418,109.408 ; C9.1@184.973,109.408 C9.1@184.973,109.803 ; C9.1@184.973,109.803 185.023,109.803 C9.1@185.418,109.408 ; C9.1@185.418,109.408 C9.1@185.481,109.345 ; 185.481,99.68 185.481,99.756 ; 185.481,99.68 185.898,99.68 185.898,99.248 ; 185.481,99.756 D7.1@185.481,100.264 ; 185.481,99.756 185.989,99.756 ; D7.1@185.481,100.264 185.989,100.264 ; D7.1@185.481,100.264 D7.1@185.481,100.772 ; D7.1@185.481,100.772 185.989,100.772 ; D7.1@185.481,100.772 D7.1@185.481,101.28 ; D7.1@185.481,101.28 185.989,101.28 ; D7.1@185.481,101.28 D7.1@185.481,101.788 ; D7.1@185.481,101.788 185.481,102.09 ; 185.481,102.09 cw(c186.046,102.55) 185.449,102.132 ccw(c186.046,102.55) 185.481,102.09 ; 185.481,102.09 ccw(c186.046,102.55) 185.531,102.035 ; 185.481,102.09 ccw(c186.046,102.55) 185.531,102.035 ; 185.481,105.888 pad.@185.989,105.888 ; 185.481,105.888 C26.1@185.481,106.36 ; C26.1@185.481,106.36 pad.@185.989,106.36 ; C26.1@185.481,106.36 C26.1@185.481,106.744 ; C26.1@185.481,106.744 185.989,106.744 ; 185.481,108.747 C9.1@185.481,108.9 ; 185.481,108.747 185.989,108.747 ; C9.1@185.481,108.9 C9.1@185.481,109.345 ; C9.1@185.481,108.9 C9.1@185.926,108.9 ; C9.1@185.481,109.345 C9.1@185.926,108.9 ; 185.531,102.035 185.629,101.936 186.286,101.28 ; 185.898,96.708 185.989,96.708 ; 185.898,96.708 pad.@185.898,97.216 ; 185.898,96.708 185.989,96.708 ; pad.@185.898,97.216 pad.@185.989,97.216 ; 185.898,99.18 ccw(c186.119,98.486) 185.894,99.179 cw(c186.119,98.486) 185.898,99.18 ; 185.898,99.18 cw(c186.119,98.486) 185.989,99.203 ; 185.898,99.18 cw(c186.119,98.486) 185.989,99.203 ; 185.898,99.18 185.898,99.248 ; 185.898,99.248 185.989,99.248 ; C9.1@185.926,108.9 C9.1@185.989,108.837 ; 185.989,96.708 186.497,96.708 ; 185.989,96.708 pad.@185.989,97.216 ; 185.989,96.708 186.497,96.708 ; pad.@185.989,97.216 186.497,97.216 ; 185.989,99.203 cw(c186.119,98.486) 186.119,99.215 ; 185.989,99.203 cw(c186.119,98.486) 186.119,99.215 ; 185.989,99.203 185.989,99.248 ; 185.989,99.248 185.989,99.756 ; 185.989,99.248 186.454,99.248 ; 185.989,99.756 185.989,100.264 ; 185.989,99.756 186.473,99.756 ; 185.989,100.264 186.473,100.264 ; 185.989,100.264 185.989,100.772 ; 185.989,100.772 186.473,100.772 ; 185.989,100.772 185.989,101.28 ; 185.989,101.28 186.286,101.28 ; pad.@185.989,105.888 pad.@185.989,106.36 ; pad.@185.989,105.888 186.489,105.888 186.489,106.36 ; pad.@185.989,106.36 185.989,106.744 ; pad.@185.989,106.36 186.256,106.36 186.489,106.36 ; 185.989,106.744 186.152,106.744 186.152,106.868 ; 185.989,108.747 186.079,108.747 ; 185.989,108.747 C9.1@185.989,108.837 ; C9.1@185.989,108.837 186.079,108.747 ; 186.079,108.747 186.152,108.675 186.152,108.392 ; 186.119,99.215 186.454,99.215 186.454,99.248 ; 186.152,106.868 186.152,107.376 ; 186.152,106.868 186.489,106.868 ; 186.152,107.376 186.152,107.884 ; 186.152,107.376 186.489,107.376 ; 186.152,107.884 186.497,107.884 ; 186.152,107.884 186.152,108.392 ; 186.152,108.392 186.497,108.392 ; 186.286,101.28 186.328,101.238 ; 186.328,101.238 ccw(c186.843,101.753) 186.473,101.125 ; 186.328,101.238 ccw(c186.843,101.753) 186.473,101.125 ; 186.473,99.756 186.473,100.264 ; 186.473,100.264 186.473,100.772 ; 186.473,100.772 186.473,101.125 ; 186.473,101.125 ccw(c186.843,101.753) 186.479,101.122 cw(c186.843,101.753) 186.473,101.125 ; 186.489,106.36 186.489,106.593 186.489,106.868 ; 186.489,106.868 186.489,107.376 ; 186.489,107.376 186.489,107.862 186.497,107.862 ; 186.497,96.708 186.497,97.216 ; 186.497,96.708 187.005,96.708 ; 186.497,96.708 187.005,96.708 ; 186.497,97.216 187.005,97.216 ; 186.497,97.216 186.497,97.529 ; 186.497,97.529 187.005,97.529 ; 186.497,107.862 186.929,107.862 186.929,107.884 ; 186.497,107.862 186.497,107.884 ; 186.497,107.884 186.929,107.884 ; 186.497,107.884 186.497,108.392 ; 186.497,108.392 186.719,108.392 ; 186.497,108.392 186.497,108.631 ; 186.497,108.631 186.719,108.631 186.719,108.392 ; 186.719,108.392 186.719,108.156 186.929,108.156 186.929,107.884 ; 187.005,96.708 187.513,96.708 ; 187.005,96.708 187.513,96.708 ; 187.005,96.708 187.005,97.216 ; 187.005,97.216 187.005,97.529 ; 187.005,97.216 R14.1@187.513,97.216 ; 187.005,97.529 R14.1@187.513,97.529 ; 187.513,96.708 187.513,97.13 R14.1@187.513,97.216 ; 187.513,96.708 188.021,96.708 ; 187.513,96.708 188.021,96.708 ; R14.1@187.513,97.216 R14.1@187.513,97.529 ; R14.1@187.513,97.216 188.021,97.216 ; R14.1@187.513,97.529 188.021,97.529 ; 188.021,96.708 188.021,97.13 188.021,97.216 ; 188.021,96.708 188.529,96.708 ; 188.021,96.708 188.529,96.708 ; 188.021,97.216 188.021,97.529 ; 188.021,97.216 188.529,97.216 ; 188.021,97.529 188.529,97.529 ; 188.529,96.708 188.529,97.13 188.529,97.216 ; 188.529,96.708 189.037,96.708 ; 188.529,96.708 189.037,96.708 ; 188.529,97.216 188.529,97.529 ; 188.529,97.216 C14.1@189.037,97.216 ; 188.529,97.529 188.558,97.529 188.558,97.614 C14.1@189.037,97.614 ; 189.037,96.708 189.037,97.13 C14.1@189.037,97.216 ; 189.037,96.708 189.545,96.708 ; 189.037,96.708 189.545,96.708 ; C14.1@189.037,97.216 C14.1@189.037,97.614 ; C14.1@189.037,97.216 C14.1@189.169,97.216 C14.1@189.545,97.216 ; 189.277,100.895 ccw(c188.907,100.267) 189.272,100.898 cw(c188.907,100.267) 189.277,100.895 ; 189.277,100.895 cw(c188.907,100.267) 189.422,100.782 ; 189.277,100.895 cw(c188.907,100.267) 189.422,100.782 ; 189.277,100.895 189.277,101.28 ; 189.277,101.28 189.545,101.28 ; 189.277,101.28 189.277,101.788 ; 189.277,101.788 189.277,102.296 ; 189.277,101.788 189.545,101.788 ; 189.277,102.296 189.545,102.296 ; 189.422,100.782 189.432,100.772 ; 189.432,100.772 189.545,100.772 ; 189.432,100.772 189.545,100.659 ; 189.545,96.708 190.053,96.708 ; 189.545,96.708 190.053,96.708 ; 189.545,96.708 C14.1@189.545,97.216 ; C14.1@189.545,97.216 189.545,97.384 C14.1@189.545,97.485 ; C14.1@189.545,97.216 190.053,97.216 ; C14.1@189.545,97.485 ccw(c189.924,98.107) 189.834,97.384 ; C14.1@189.545,97.485 ccw(c189.924,98.107) 189.834,97.384 ; C14.1@189.545,97.485 cw(c189.924,98.107) 189.409,97.592 ccw(c189.924,98.107) C14.1@189.545,97.485 ; 189.545,100.659 189.545,100.772 ; 189.545,100.659 189.94,100.264 ; 189.545,100.772 189.545,101.28 ; 189.545,100.772 190.053,100.772 ; 189.545,101.28 189.545,101.788 ; 189.545,101.28 190.053,101.28 ; 189.545,101.788 189.545,102.296 ; 189.545,101.788 190.053,101.788 ; 189.545,102.296 189.545,102.318 ; 189.545,102.296 190.053,102.296 ; 189.545,102.318 190.053,102.318 ; 189.834,97.384 ccw(c189.924,98.107) 189.924,97.378 ; 189.834,97.384 ccw(c189.924,98.107) 189.924,97.378 ; 189.924,97.378 190.053,97.378 ; 189.94,100.264 190.053,100.264 ; 189.94,100.264 190.053,100.151 ; 190.053,96.708 190.053,97.216 ; 190.053,96.708 190.561,96.708 ; 190.053,96.708 190.561,96.708 ; 190.053,97.216 190.053,97.378 ; 190.053,97.216 190.561,97.216 ; 190.053,100.151 190.053,100.264 ; 190.053,100.151 190.361,99.843 ; 190.053,100.264 190.053,100.772 ; 190.053,100.264 190.561,100.264 ; 190.053,100.772 190.053,101.28 ; 190.053,100.772 190.561,100.772 ; 190.053,101.28 190.053,101.788 ; 190.053,101.28 190.561,101.28 ; 190.053,101.788 190.053,102.296 ; 190.053,101.788 pad.@190.561,101.788 ; 190.053,102.296 190.053,102.318 ; 190.053,102.296 pad.@190.561,102.296 ; 190.053,102.318 190.561,102.318 ; 190.361,99.843 cw(c190.905,99.484) 190.56,100.037 cw(c190.905,99.484) 190.561,100.037 ; 190.561,96.708 190.561,97.216 ; 190.561,96.708 191.069,96.708 ; 190.561,96.708 191.069,96.708 ; 190.561,97.216 191.069,97.216 ; 190.561,97.216 190.561,97.331 ; 190.561,97.331 ccw(c190.905,97.884) 190.905,97.232 191.069,97.232 ; 190.561,100.037 cw(c190.905,99.484) 190.905,100.136 191.069,100.136 ; 190.561,100.037 190.561,100.264 ; 190.561,100.264 191.069,100.264 ; 190.561,100.264 190.561,100.772 ; 190.561,100.772 191.069,100.772 ; 190.561,100.772 190.561,101.28 ; 190.561,101.28 191.069,101.28 ; 190.561,101.28 pad.@190.561,101.788 ; pad.@190.561,101.788 191.069,101.788 ; pad.@190.561,101.788 pad.@190.561,102.296 ; pad.@190.561,102.296 190.561,102.318 ; pad.@190.561,102.296 191.069,102.296 ; 190.561,102.318 191.069,102.318 ; 191.069,96.708 191.069,97.216 ; 191.069,96.708 191.577,96.708 ; 191.069,96.708 191.577,96.708 ; 191.069,97.216 191.069,97.232 ; 191.069,97.216 191.577,97.216 ; 191.069,97.232 191.577,97.232 ; 191.069,100.136 191.069,100.264 ; 191.069,100.136 191.372,100.136 ; 191.069,100.264 191.069,100.772 ; 191.069,100.264 191.407,100.264 ; 191.069,100.772 191.577,100.772 ; 191.069,100.772 191.069,101.28 ; 191.069,101.28 191.577,101.28 ; 191.069,101.28 191.069,101.788 ; 191.069,101.788 191.577,101.788 ; 191.069,101.788 191.069,102.296 ; 191.069,102.296 191.577,102.296 ; 191.069,102.296 191.069,102.318 ; 191.069,102.318 191.577,102.318 ; 191.372,100.136 cw(c192.336,99.942) 191.407,100.264 ; 191.407,100.264 cw(c192.336,99.942) 191.577,100.566 ; 191.577,96.708 191.577,97.216 ; 191.577,96.708 192.085,96.708 ; 191.577,96.708 192.085,96.708 ; 191.577,97.216 191.577,97.232 ; 191.577,97.216 192.085,97.216 ; 191.577,97.232 191.855,97.232 ccw(c191.855,97.884) 192.085,97.274 ; 191.577,100.566 cw(c192.336,99.942) 191.81,100.772 ; 191.577,100.566 191.577,100.772 ; 191.577,100.772 191.577,101.28 ; 191.577,100.772 191.81,100.772 ; 191.577,101.28 191.577,101.788 ; 191.577,101.28 C16.1@192.085,101.28 ; 191.577,101.788 191.577,102.296 ; 191.577,101.788 192.085,101.788 ; 191.577,102.296 191.577,102.318 ; 191.81,100.772 cw(c192.336,99.942) C16.1@192.085,100.892 ; 192.085,96.708 192.085,97.216 ; 192.085,96.708 192.593,96.708 ; 192.085,96.708 192.593,96.708 ; 192.085,97.216 192.339,97.216 192.593,97.216 ; 192.085,97.216 192.085,97.274 ; C16.1@192.085,100.892 cw(c192.336,99.942) C16.1@192.593,100.89 ; C16.1@192.085,100.892 C16.1@192.085,101.28 ; C16.1@192.085,101.28 192.085,101.788 ; C16.1@192.085,101.28 C16.1@192.593,101.28 ; 192.085,101.788 192.085,102.291 ; 192.085,101.788 192.593,101.788 ; 192.085,102.291 192.593,102.291 ; 192.593,96.708 192.847,96.708 ; 192.593,96.708 192.593,96.962 192.593,97.216 ; 192.593,96.708 192.847,96.708 ; 192.593,97.216 192.593,97.305 ; 192.593,97.216 193.101,97.216 ; 192.593,97.305 193.101,97.305 ; C16.1@192.593,100.89 C16.1@192.593,101.28 ; C16.1@192.593,101.28 192.593,101.788 ; C16.1@192.593,101.28 C16.1@192.799,101.28 ; 192.593,101.788 192.593,102.291 ; 192.593,101.788 192.799,101.788 ; 192.593,102.291 193.101,102.291 ; C16.1@192.799,101.28 192.799,101.788 ; 192.799,101.788 192.799,102.205 193.101,102.205 ; 192.847,96.708 193.101,96.708 ; 192.847,96.708 193.101,96.708 ; 193.101,96.708 193.101,97.216 ; 193.101,96.708 193.609,96.708 ; 193.101,96.708 193.609,96.708 ; 193.101,97.216 193.101,97.305 ; 193.101,97.216 193.609,97.216 ; 193.101,97.305 193.609,97.305 ; 193.101,102.205 193.609,102.205 ; 193.101,102.205 193.101,102.291 ; 193.101,102.291 193.609,102.291 ; 193.609,96.708 193.609,97.216 ; 193.609,96.708 194.117,96.708 ; 193.609,96.708 194.117,96.708 ; 193.609,97.216 194.117,97.216 ; 193.609,97.216 193.609,97.305 ; 193.609,97.305 194.117,97.305 ; 193.609,102.205 194.117,102.205 ; 193.609,102.205 193.609,102.291 ; 193.609,102.291 194.117,102.291 ; 194.117,96.708 194.117,97.216 ; 194.117,96.708 194.47,96.708 ; 194.117,96.708 194.47,96.708 ; 194.117,97.216 194.117,97.305 ; 194.117,97.216 194.204,97.216 ; 194.117,102.205 194.625,102.205 ; 194.117,102.205 194.117,102.291 ; 194.117,102.291 194.625,102.291 ; 194.204,97.216 ccw(c194.855,97.234) 194.47,96.708 ; 194.625,102.205 194.625,102.291 ; 194.625,102.291 194.957,102.291 194.957,102.296 ; 194.957,102.296 195.034,102.296 ; 194.957,102.296 194.957,102.563 ccw(c195.851,102.677) 195.034,102.296 ; 194.957,103.182 ccw(c195.433,103.947) 195.066,103.123 cw(c195.433,103.947) 194.957,103.182 ; 194.957,103.182 cw(c195.433,103.947) 194.955,103.182 ccw(c195.433,103.947) 194.957,103.182 ; 195.034,102.296 ccw(c195.851,102.677) 195.133,102.132 ; 195.133,101.932 cw(c194.752,101.026) 195.372,101.788 ; 195.133,101.932 195.133,102.132 ; 195.133,102.132 ccw(c195.851,102.677) 195.641,101.8 ; 195.372,100.264 ccw(c194.752,101.026) 195.641,100.607 ; 195.372,100.264 195.641,100.264 ; 195.372,101.788 cw(c194.752,101.026) 195.641,101.445 ; 195.372,101.788 195.641,101.788 ; 195.641,100.136 195.641,100.264 ; 195.641,100.136 195.805,100.136 cw(c195.805,99.484) 196.033,100.094 ; 195.641,100.264 196.033,100.264 ; 195.641,100.264 195.641,100.607 ; 195.641,100.607 ccw(c194.752,101.026) 195.701,100.772 ; 195.641,101.445 cw(c194.752,101.026) 195.701,101.28 ; 195.641,101.445 195.641,101.788 ; 195.641,101.788 195.641,101.8 ; 195.641,101.788 195.701,101.788 ; 195.641,101.8 ccw(c195.851,102.677) 195.701,101.788 ; 195.701,100.772 ccw(c194.752,101.026) 195.735,101.026 ccw(c194.752,101.026) 195.701,101.28 ; 195.701,100.772 196.149,100.772 ; 195.701,101.28 196.149,101.28 ; 195.701,101.788 ccw(c195.851,102.677) 195.851,101.775 196.149,101.775 ; 196.033,100.094 196.033,100.264 ; 196.033,100.264 196.033,100.3 196.149,100.3 ; 196.149,100.3 196.149,100.772 ; 196.149,100.3 196.657,100.3 ; 196.149,100.772 196.657,100.772 ; 196.149,100.772 196.149,101.28 ; 196.149,101.28 196.657,101.28 ; 196.149,101.28 196.149,101.775 ; 196.149,101.775 196.657,101.775 ; 196.657,100.3 197.165,100.3 ; 196.657,100.3 196.657,100.772 ; 196.657,100.772 196.657,101.28 ; 196.657,100.772 C111.1@197.165,100.772 ; 196.657,101.28 196.657,101.775 ; 196.657,101.28 C111.1@197.165,101.28 ; 196.657,101.775 197.165,101.775 ; 197.165,100.3 C111.1@197.165,100.772 ; 197.165,100.3 197.56,100.3 C111.1@197.56,100.772 ; C111.1@197.165,100.772 C111.1@197.56,100.772 ; C111.1@197.165,100.772 C111.1@197.165,101.28 ; C111.1@197.165,101.28 C111.1@197.56,101.28 ; C111.1@197.165,101.28 197.165,101.775 ; C111.1@197.56,100.772 C111.1@197.56,101.28 ; 197.975,96.708 C18.1@197.975,97.216 ; 197.975,96.708 198.181,96.708 ; 197.975,96.708 198.181,96.708 ; C18.1@197.975,97.216 C18.1@198.181,97.216 ; C18.1@197.975,97.216 197.975,97.361 C18.1@198.181,97.567 ; 198.072,103.406 ccw(c197.351,103.947) 198.181,103.595 ; 198.072,103.406 198.181,103.406 ; 198.181,96.708 C18.1@198.181,97.216 ; 198.181,96.708 198.227,96.708 ; 198.181,96.708 198.227,96.708 ; C18.1@198.181,97.216 198.246,97.216 C18.1@198.689,97.216 ; C18.1@198.181,97.216 C18.1@198.181,97.567 ; C18.1@198.181,97.567 198.201,97.587 C18.1@198.689,97.587 ; 198.181,103.406 198.689,103.406 ; 198.181,103.406 198.181,103.595 ; 198.181,103.595 ccw(c197.351,103.947) 198.244,103.82 ; 198.227,96.708 198.689,96.708 ; 198.227,96.708 198.689,96.708 ; 198.244,103.82 198.689,103.82 ; 198.28,104.328 cw(c197.862,105.217) 198.182,104.288 ccw(c197.862,105.217) 198.28,104.328 ; 198.28,104.328 ccw(c197.862,105.217) 198.48,104.453 cw(c197.862,105.217) 198.28,104.328 ; 198.28,104.328 198.62,104.328 ; 198.62,104.328 ccw(c199.188,105.13) 198.689,104.284 ; 198.62,104.328 ccw(c199.188,105.13) 198.689,104.284 ; 198.62,104.328 cw(c199.188,105.13) 198.482,104.447 ccw(c199.188,105.13) 198.62,104.328 ; 198.689,96.708 C18.1@198.689,97.216 ; 198.689,96.708 199.197,96.708 ; 198.689,96.708 199.197,96.708 ; C18.1@198.689,97.216 199.197,97.216 ; C18.1@198.689,97.216 C18.1@198.689,97.587 ; C18.1@198.689,97.587 198.988,97.587 199.273,97.302 199.273,97.216 ; 198.689,103.406 198.689,103.82 ; 198.689,103.406 199.197,103.406 ; 198.689,103.82 199.197,103.82 ; 198.689,103.82 198.689,104.284 ; 198.689,104.284 ccw(c199.188,105.13) 199.197,104.147 ; 198.689,104.284 ccw(c199.188,105.13) 199.197,104.147 ; 199.197,96.708 199.197,97.216 ; 199.197,96.708 199.273,96.708 ; 199.197,96.708 199.273,96.708 ; 199.197,97.216 199.273,97.216 ; 199.197,103.406 199.705,103.406 ; 199.197,103.406 199.197,103.82 ; 199.197,103.82 199.705,103.82 ; 199.197,103.82 199.197,104.147 ; 199.197,104.147 ccw(c199.188,105.13) 199.206,104.147 ; 199.197,104.147 ccw(c199.188,105.13) 199.206,104.147 ; 199.206,104.147 ccw(c199.188,105.13) 199.705,104.294 ; 199.206,104.147 ccw(c199.188,105.13) 199.705,104.294 ; 199.273,96.708 199.273,97.216 ; 199.564,101.788 199.564,101.948 199.705,101.948 ; 199.705,101.824 200.213,101.824 ; 199.705,101.824 199.705,101.948 ; 199.705,101.948 200.213,101.948 ; 199.705,103.406 199.705,103.82 ; 199.705,103.406 200.213,103.406 ; 199.705,103.82 pad.@200.213,103.82 ; 199.705,103.82 199.705,104.294 ; 199.705,104.294 ccw(c199.188,105.13) 199.757,104.328 ; 199.705,104.294 ccw(c199.188,105.13) 199.757,104.328 ; 199.757,104.328 ccw(c199.188,105.13) 199.884,104.436 ; 199.757,104.328 pad.@200.213,104.328 ; 199.952,108.392 cw(c199.248,107.706) 200.213,107.891 ; 199.952,108.392 cw(c199.248,107.706) 200.213,107.891 ; 199.952,108.392 ccw(c199.248,107.706) 199.943,108.401 cw(c199.248,107.706) 199.952,108.392 ; 199.952,108.392 200.213,108.392 ; 200.165,104.836 cw(c199.248,105.189) 199.943,104.495 ccw(c199.248,105.189) 200.165,104.836 ; 200.165,104.836 ccw(c199.248,105.189) 200.213,105.004 ; 200.165,104.836 ccw(c199.248,105.189) 200.213,105.004 ; 200.165,104.836 200.213,104.836 ; 200.213,101.824 200.721,101.824 ; 200.213,101.824 200.213,101.948 ; 200.213,101.948 200.721,101.948 ; 200.213,103.406 pad.@200.213,103.82 ; 200.213,103.406 200.721,103.406 ; pad.@200.213,103.82 200.658,103.82 ; pad.@200.213,103.82 pad.@200.213,104.328 ; pad.@200.213,104.328 200.213,104.836 ; pad.@200.213,104.328 200.467,104.328 200.499,104.328 200.721,104.328 ; 200.213,104.836 200.467,104.836 200.721,104.836 ; 200.213,104.836 200.213,105.004 ; 200.213,105.004 ccw(c199.248,105.189) 200.231,105.189 ; 200.213,105.004 ccw(c199.248,105.189) 200.231,105.189 ; 200.213,107.891 cw(c199.248,107.706) 200.214,107.884 ; 200.213,107.891 cw(c199.248,107.706) 200.214,107.884 ; 200.213,107.891 200.213,108.392 ; 200.213,108.392 C21.1@200.721,108.392 ; 200.213,108.392 200.213,108.631 ; 200.213,108.631 C21.1@200.721,108.631 ; 200.214,107.884 cw(c199.248,107.706) 200.231,107.706 ; 200.214,107.884 cw(c199.248,107.706) 200.231,107.706 ; 200.214,107.884 200.543,107.884 C21.1@200.721,107.884 ; 200.231,105.189 200.231,105.344 ; 200.231,105.344 200.231,105.852 ; 200.231,105.344 200.467,105.344 200.721,105.344 ; 200.231,105.852 200.231,106.36 ; 200.231,105.852 200.467,105.852 200.721,105.852 ; 200.231,106.36 200.231,106.868 ; 200.231,106.36 200.467,106.36 200.658,106.36 ; 200.231,106.868 200.231,107.376 ; 200.231,106.868 200.467,106.868 200.721,106.868 ; 200.231,107.376 200.467,107.376 200.721,107.376 ; 200.231,107.376 200.231,107.706 ; 200.658,103.82 ccw(c201.551,103.947) 200.721,103.595 ; 200.658,103.82 cw(c201.551,103.947) 200.721,104.299 ; 200.658,106.36 ccw(c201.551,106.487) 200.721,106.135 ; 200.658,106.36 cw(c201.551,106.487) 200.658,106.362 cw(c201.551,106.487) 200.721,106.839 ; 200.721,101.824 200.721,101.948 ; 200.721,101.824 201.26,101.824 ; 200.721,103.406 200.83,103.406 ; 200.721,103.406 200.721,103.595 ; 200.721,103.595 ccw(c201.551,103.947) 200.83,103.406 ; 200.721,104.299 cw(c201.551,103.947) 200.734,104.328 ; 200.721,104.299 200.721,104.328 ; 200.721,104.328 200.721,104.55 200.721,104.836 ; 200.721,104.328 200.734,104.328 ; 200.721,104.836 200.721,105.344 ; 200.721,104.836 201.007,104.836 201.229,104.836 ; 200.721,105.344 200.975,105.344 201.229,105.344 ; 200.721,105.344 200.721,105.598 200.721,105.852 ; 200.721,105.852 200.721,106.135 ; 200.721,105.852 200.911,105.852 ; 200.721,106.135 ccw(c201.551,106.487) 200.911,105.852 ; 200.721,106.839 cw(c201.551,106.487) 200.734,106.868 ; 200.721,106.839 200.721,106.868 ; 200.721,106.868 200.721,107.376 ; 200.721,106.868 200.734,106.868 ; 200.721,107.376 C21.1@200.721,107.884 ; 200.721,107.376 201.229,107.376 ; C21.1@200.721,107.884 200.721,108.062 C21.1@200.721,108.392 ; C21.1@200.721,107.884 C21.1@201.229,107.884 ; C21.1@200.721,108.392 C21.1@201.051,108.392 C21.1@201.229,108.392 ; C21.1@200.721,108.392 C21.1@200.721,108.631 ; C21.1@200.721,108.631 C21.1@201.229,108.631 ; 200.734,104.328 cw(c201.551,103.947) 201.229,104.789 ; 200.734,106.868 cw(c201.551,106.487) 201.229,107.329 ; 200.911,105.852 ccw(c201.551,106.487) 201.229,105.645 ; 201.229,104.789 cw(c201.551,103.947) 201.401,104.836 ; 201.229,104.789 201.229,104.836 ; 201.229,104.836 201.229,105.217 201.229,105.344 ; 201.229,104.836 201.401,104.836 ; 201.229,105.344 IC7.3@201.737,105.344 ; 201.229,105.344 201.229,105.645 ; 201.229,105.645 ccw(c201.551,106.487) 201.551,105.585 201.737,105.585 ; 201.229,107.329 cw(c201.551,106.487) 201.401,107.376 ; 201.229,107.329 201.229,107.376 ; 201.229,107.376 C21.1@201.229,107.884 ; 201.229,107.376 201.401,107.376 ; C21.1@201.229,107.884 201.737,107.884 ; C21.1@201.229,107.884 C21.1@201.229,108.392 ; C21.1@201.229,108.392 201.737,108.392 ; C21.1@201.229,108.392 C21.1@201.229,108.631 ; C21.1@201.229,108.631 201.737,108.631 ; 201.26,101.824 ccw(c201.551,102.677) 201.551,101.775 201.658,101.775 ; 201.401,104.836 cw(c201.551,103.947) 201.551,104.849 201.737,104.849 ; 201.401,107.376 cw(c201.551,106.487) 201.551,107.389 201.737,107.389 ; 201.658,100.264 201.737,100.264 ; 201.658,100.264 201.658,100.173 201.737,100.173 ; 201.658,100.264 C17.1@201.658,100.772 ; C17.1@201.658,100.772 C17.1@201.737,100.772 ; C17.1@201.658,100.772 201.658,101.28 ; 201.658,101.28 201.737,101.28 ; 201.658,101.28 201.658,101.775 ; 201.658,101.775 201.737,101.775 ; 201.737,100.173 201.737,100.264 ; 201.737,100.173 202.245,100.173 ; 201.737,100.264 C17.1@201.737,100.772 ; 201.737,100.264 202.245,100.264 ; C17.1@201.737,100.772 C17.1@202.056,100.772 C17.1@202.245,100.772 ; C17.1@201.737,100.772 201.737,101.28 ; 201.737,101.28 201.737,101.775 ; 201.737,101.28 202.245,101.28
